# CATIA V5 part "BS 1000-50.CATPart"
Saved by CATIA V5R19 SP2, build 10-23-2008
Part number: BS 1000-50
Bounding box of the stored display mesh (mm): x -24.865 to 24.865, y -24.997 to 24.997, z 0 to 138
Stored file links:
  C:\Users\Bora\Desktop\3D Katı model\BS serisi\BS 1000\BS 1000-50.CATPart
  C:\Program Files\Dassault Systemes\B19\intel_a\reffiles\standard\MetricThickPitch.txt
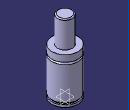
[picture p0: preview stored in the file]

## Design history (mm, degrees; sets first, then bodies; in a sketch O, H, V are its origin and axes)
Body1 (main body)
  Sketch1 on yz-plane, origin (0, 0, 0), H (0, 1, 0), V (0, 0, 1)
    point P2 (14, 136)
    line L1 (14, 136) -> (14, 87)
    point P3 (25, 74.5)
    line L2 (25, 87) -> (25, 74.5)
    point P6 (25, 70.5)
    line L3 (25, 70.5) -> (25, 7.5)
    line L4 (25, 4) -> (25, 0)
    point P9 (25, 70.5)
    point P10 (25, 74.5)
    arc A1 centre (25, 72.5) radius 2 from (25, 74.5) to (25, 70.5) ccw
    point P12 (14, 136)
    arc A2 centre (12, 136) radius 2 from (14, 136) to (12, 138) ccw
    point P13 (22.5, 4)
    point P14 (22.5, 4)
    line L5 (22.5, 7.5) -> (22.5, 4)
    line L6 (12, 138) -> (0, 138)
    point P16 (0, 138)
    line L7 (14, 87) -> (25, 87)
    line L8 (22.5, 7.5) -> (25, 7.5)
    line L9 (22.5, 4) -> (25, 4)
    line L10 (25, 0) -> (0, 0)
    coincidence: P16 V, P2 P12, P3 P10, P6 P9, P13 P14
    tangency: L6 A2
    horizontal: L7 H, L8 H, L9 H, L10 H
  Shaft1: profile Sketch1, axis Sketch1.V, angle 360
  Sketch2 on face of Shaft1 from Sketch1.L10, origin (0, 0, 0), H (1, 0, 0), V (0, -1, 0)
    point P1 (10, 0)
    distance P1 V = 10
  Hole1: placed by Sketch2, at (10, 0, 0) direction (0, 0, 1), diameter 6.647, depth 6, threaded "M8", thread diameter 8, thread depth 6, pitch 1.25
  CircPattern1: of Hole1, instances 2, angular step 180, axis from xy-plane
